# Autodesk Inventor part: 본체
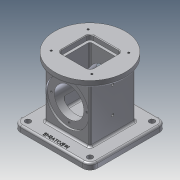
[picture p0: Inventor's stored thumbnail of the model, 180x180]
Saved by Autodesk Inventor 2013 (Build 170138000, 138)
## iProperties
Created: 2021-05
Part Number: 본체
Material: 알루미늄 6061
Document SubType Name: Modeling
Designer: user
Density: 2.71 g/cm^3
Mass: 1256.26 g
Surface Area: 895.532 cm^2
Volume: 463.564 cm^3
Author: user
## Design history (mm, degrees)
sketch "스케치1"
  geometry: L1 (62.5, -62.5)-(-62.5, -62.5); L2 (-62.5, -62.5)-(-62.5, 62.5); L3 (-62.5, 62.5)-(62.5, 62.5); L4 (62.5, 62.5)-(62.5, -62.5); L5 (62.5, -62.5)-(-62.5, 62.5); L6 (-62.5, -62.5)-(62.5, 62.5); 1 further point
  constraints: 12 end point, 2 midpoint, 2 parallel, 1 horizontal, 1 perpendicular
  dimensions: "d0" = 125 distance of L1.start L1.end; "d2" = 125 distance of L1.end L2.end
extrude "돌출1" new body sketch "스케치1" distance "d3" = 10; taper "d4" = 0 deg
node "작업 평면2"
sketch "스케치2"
  geometry: C1 r 57.5 at (0, 0); 1 further point
  constraints: 1 centre point, 1 coincident
  dimensions: "d7" = 115 diameter of C1
extrude "돌출2" join sketch "스케치2" distance "d8" = 10; taper "d9" = 0 deg
sketch "스케치3"
  geometry: L1 (-37, 37)-(37, 37); L2 (37, 37)-(37, -37); L3 (37, -37)-(-37, -37); L4 (-37, -37)-(-37, 37); L5 (-37, 37)-(37, -37); L6 (37, 37)-(-37, -37); 1 further point
  constraints: 12 end point, 2 midpoint, 2 parallel, 1 horizontal, 1 perpendicular
  dimensions: "d10" = 74 distance of L1.start L1.end; "d12" = 74 distance of L1.end L2.end
extrude "돌출3" join sketch "스케치3" stored distance "d13" = 10; taper "d14" = 0 deg
sketch "스케치4"
  geometry: L1 (-26, 26)-(26, 26); L2 (26, 26)-(26, -26); L3 (26, -26)-(-26, -26); L4 (-26, -26)-(-26, 26); L5 (-26, 26)-(26, -26); L6 (26, 26)-(-26, -26); C1 r 57.5 at (0, 0) reference
  constraints: 12 end point, 2 midpoint, 2 parallel, 1 horizontal, 1 perpendicular
  dimensions: "d15" = 52 distance of L2.end L3.end; "d16" = 52 distance of L1.end L2.end
extrude "돌출4" cut sketch "스케치4" distance "d17" = 8; taper "d18" = 0 deg
sketch "스케치5"
  geometry: L1 (-22, 22)-(22, 22); L2 (22, 22)-(22, -22); L3 (22, -22)-(-22, -22); L4 (-22, -22)-(-22, 22); L5 (-22, 22)-(22, -22); L6 (22, 22)-(-22, -22); 1 further point
  constraints: 12 end point, 2 midpoint, 2 parallel, 1 horizontal, 1 perpendicular
  dimensions: "d19" = 44 distance of L1.start L1.end; "d21" = 44 distance of L1.end L2.end
extrude "돌출5" cut sketch "스케치5" distance "d22" = 74; taper "d23" = 0 deg
sketch "스케치6"
  geometry: C1 r 28 at (0, 0); 1 further point
  constraints: 1 centre point, 1 coincident
  dimensions: "d24" = 56 diameter of C1
extrude "돌출6" cut sketch "스케치6" distance "d25" = 18; taper "d26" = 0 deg
sketch "스케치7"
  geometry: L1 (0, 0)-(0, 88) reference; C1 r 35 at (37, 44); 2 further points
  constraints: 1 centre point, 1 horizontal alignment, 1 midpoint
  dimensions: "d27" = 70 diameter of C1
extrude "돌출7" cut sketch "스케치7" distance "d28" = 3; taper "d29" = 0 deg
sketch "스케치8"
  geometry: C1 r 35 at (0, 0) reference; C2 r 24 at (0, 0); 1 further point
  constraints: 1 centre point, 1 coincident
  dimensions: "d30" = 48 diameter of C2
extrude "돌출8" cut sketch "스케치8" distance "d31" = 100; taper "d32" = 0 deg
fillet "모깎기1" dims "d33" = 12
sketch "스케치9"
  geometry: A1 r 12 centre (-50.5, 50.5) between (-50.5, 62.5) and (-62.5, 50.5) reference; A2 r 12 centre (-50.5, -50.5) between (-62.5, -50.5) and (-50.5, -62.5) reference; A3 r 12 centre (50.5, -50.5) between (50.5, -62.5) and (62.5, -50.5) reference; A4 r 12 centre (50.5, 50.5) between (62.5, 50.5) and (50.5, 62.5) reference; 5 further points
  constraints: 4 coincident
hole "구멍1" sketch "스케치9" at (-50.5, 50.5), (-50.5, -50.5), (50.5, -50.5), (50.5, 50.5) diameter "d34" = 9; stored, may be unused: countersink angle "d38" = 90 deg, drill point angle "d40" = 118 deg; dims "d35" = 6, "d36" = 4, "d37" = 2, "d39" = 8
sketch "스케치10"
  geometry: C1 r 24 at (0, 0) reference; C2 r 35 at (0, 0) reference; A1 r 29 centre (0, 0) between (0, 29) and (-29, 0); 3 further points
  constraints: 4 point on circle, 2 horizontal alignment, 2 vertical alignment, 1 centre point, 1 coincident
  dimensions: "d41" = 58 diameter of A1
hole "구멍2" sketch "스케치10" at (0, 29), (-29, 0), (0, -29), (29, 0) diameter "d42" = 3.242; stored, may be unused: countersink angle "d46" = 90 deg, drill point angle "d48" = 118 deg; dims "d43" = 8, "d44" = 4, "d45" = 2, "d47" = 10
sketch "스케치11"
  geometry: L1 (-33, 30)-(33, 30); L2 (33, 30)-(33, -30); L3 (33, -30)-(-33, -30); L4 (-33, -30)-(-33, 30); L5 (-33, 30)-(33, -30); L6 (33, 30)-(-33, -30); C1 r 57.5 at (0, 0) reference; 4 further points
  constraints: 12 end point, 4 coincident, 2 midpoint, 2 parallel, 1 horizontal, 1 perpendicular
  dimensions: "d49" = 66 distance of L1.start L1.end; "d51" = 60 distance of L1.end L2.end
hole "구멍3" sketch "스케치11" at (-33, 30), (-33, -30), (33, -30), (33, 30) diameter "d52" = 3.242; stored, may be unused: countersink angle "d56" = 90 deg, drill point angle "d58" = 118 deg; dims "d53" = 8, "d54" = 4, "d55" = 2, "d57" = 10
node "작업 평면3"
sketch "스케치12"
  geometry: 2 further points
  constraints: 1 vertical alignment, 1 other
  dimensions: "d60" = 55 distance of point (0, 55) point (0, 0)
feature "엠보싱1" sketch "스케치12" dims "d0" = 125, "d2" = 125, "d13" = 10, "d14" = 0, "d61" = 0.5, "d62" = 0
sketch "스케치13"
  geometry: 3 further points
  constraints: 2 vertical alignment
  dimensions: "d63" = 37 distance of point (37, -10) point (37, 27); "d64" = 43 distance of point (37, 27) point (37, 70)
hole "구멍4" sketch "스케치13" at (37, 27), (37, 70) diameter "d65" = 4.134; stored, may be unused: countersink angle "d69" = 90 deg, drill point angle "d71" = 118 deg; dims "d66" = 30, "d67" = 4, "d68" = 2, "d70" = 30
fillet "모깎기2" dims "d72" = 3
fillet "모깎기3" dims "d73" = 3
fillet "모깎기4" dims "d74" = 3
fillet "모깎기5" dims "d75" = 6
fillet "모깎기6" dims "d76" = 3
chamfer "모따기1" distance "d77" = 1; stored, may be unused: second distance "d78" = 2, angle "d79" = 45 deg
feature "면 기울기1" dims angle "d80" = 10 deg
fillet "모깎기7" dims "d81" = 3
fillet "모깎기8" dims "d82" = 3
fillet "모깎기9" dims "d83" = 3
fillet "모깎기10" dims "d84" = 3
node "솔리드1"
mirror "대칭1"
mirror "대칭2"
other parameters: "d6" = 108, "d59" = 24.75
